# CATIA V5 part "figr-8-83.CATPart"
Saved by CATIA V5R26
Part number: Part1
Bounding box of the stored display mesh (mm): x -44.701 to 35.128, y -43.586 to 25.876, z -47.191 to 31.322
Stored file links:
  D:\_Deepak\CATIA\CATIA V5-6R2016_Deepak\Resources\Part files\Partfiles\c08_catia_v5_6r2016_prt\figr-8-83.CATPart
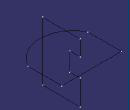
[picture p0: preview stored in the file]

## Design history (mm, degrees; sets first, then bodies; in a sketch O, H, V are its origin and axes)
Body1 (main body)
  Sketch1 on xy-plane, origin (0, 0, 0), H (1, 0, 0), V (0, 1, 0)
    line L1 (-44.7013, 25.8759) -> (35.1284, 25.8759)
    line L2 (35.1284, 25.8759) -> (35.1284, -18.9612)
    line L3 (-44.7013, 25.8759) -> (-44.7013, -18.9612)
    arc A1 centre (-4.7865, 1.0752) radius 44.6615 from (-44.7013, -18.9612) to (35.1284, -18.9612) ccw
    horizontal: L1 H
    vertical: L2 V, L3 V
  Sketch2 on yz-plane, origin (0, 0, 0), H (0, 1, 0), V (0, 0, 1)
    line L1 (-35.2302, 31.3221) -> (-35.2302, -47.1914)
    point P2 (-35.2302, -47.1914)
    point P3 (-35.2302, -47.1914)
    line L2 (-35.2302, -47.1914) -> (15.3919, -47.1914)
    point P4 (15.3919, -47.1914)
    line L3 (15.3919, 31.3221) -> (-35.2302, 31.3221)
    line L4 (15.3919, 31.3221) -> (15.3919, 10.6589)
    line L5 (15.3919, 10.6589) -> (1.7321, 10.6589)
    line L6 (1.7321, 10.6589) -> (1.7321, -13.9018)
    line L7 (1.7321, -13.9018) -> (15.3919, -13.9018)
    point P9 (15.3919, -13.9018)
    line L8 (15.3919, -13.9018) -> (15.3919, -47.1914)
    point P10 (15.3919, -47.1914)
    vertical: L1 V, L4 V, L6 V, L8 V
    horizontal: L2 H, L3 H, L5 H, L7 H
    coincidence: P9 L4, P10 L2, P10 P4, P3 P2
  SolidCombine1: FirstComponentDirection Sketch1, FirstComponentProfile Sketch1, SecondComponentDirection Sketch2, SecondComponentProfile Sketch2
